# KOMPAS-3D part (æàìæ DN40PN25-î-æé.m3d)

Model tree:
1. Объединить компоненты:1  (labels: СЕНС DN40PN25-М)
2. Эскиз:1
3. Операция выдавливания:1
     Расстояние 1 = 14
4. Фаска:1
     Угол = 45; Длина 1 = 2; Длина 2 = 2

Referenced files in D:\Савин\!СЕНСОР\3D для заказчика\!Новый перечень\СЕНС\8. СЕНС-М\DN40\: СЕНС DN40PN25-М.a3d
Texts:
  СЕНС DN40PN25-М-СВ
  ООО НПП Сенсор
  СЕНС DN40PN25-М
